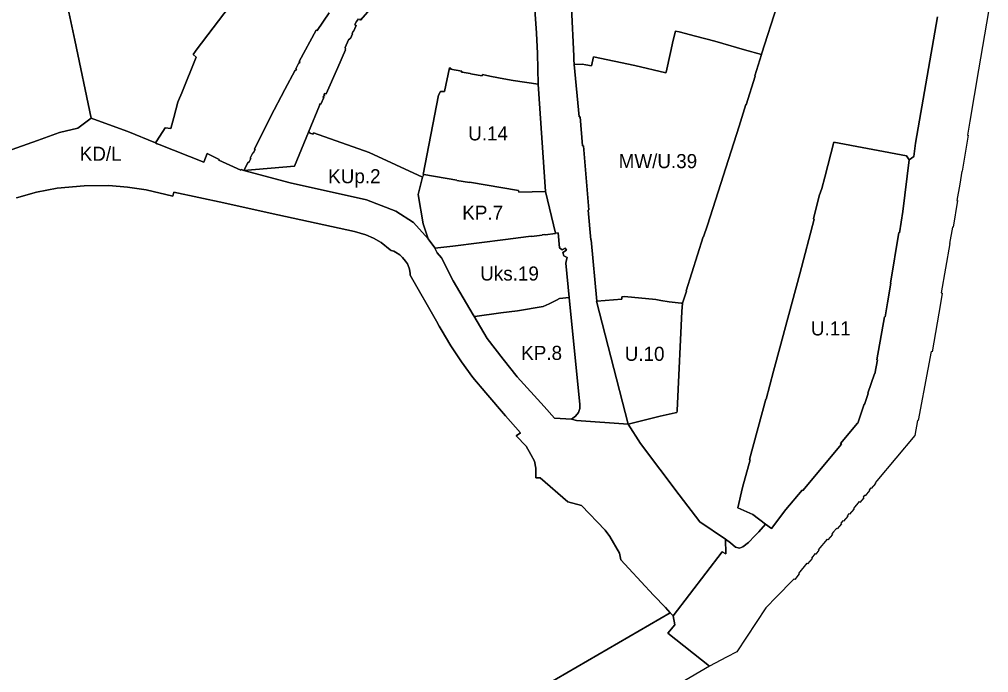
# Model space of a CAD drawing. Extents: x 7423367 to 7424726, y 5546744 to 5548391.
# Drawn here: x 7423781.7 to 7424125.7, y 5546954.8 to 5547186.6 of the extents above; entities that cross this region are included whole.
import ezdxf

# ---------------------------------------------------------------- set-up
doc = ezdxf.new("R2010")
doc.units = 0
doc.layers.add('linie_rozgraniczajace', color=7, linetype='Continuous')
doc.layers.add('oznaczenia_przeznaczen', color=7, linetype='Continuous')

msp = doc.modelspace()

# ---------------------------------------------------------------- linework, layer by layer
at = {"layer": 'linie_rozgraniczajace'}
for points in [[(7423780.9, 5547277.38), (7423781.77, 5547273.48), (7423781.99, 5547272.51), (7423786.19, 5547252.01), (7423786.97, 5547247.83), (7423787.16, 5547246.93), (7423787.29, 5547246.31), (7423798.24, 5547194.18), (7423801.4, 5547179.17), (7423807.26, 5547151.49), (7423802.44, 5547148.02), (7423795.99, 5547146.38), (7423788.2, 5547143.63), (7423771.74, 5547137.77)], [(7423858.41, 5547194.06), (7423844.47, 5547175.64), (7423844.19, 5547175.25), (7423843.38, 5547174.13), (7423844.5, 5547173.17), (7423839.34, 5547160.51), (7423838.19, 5547157.76), (7423837.93, 5547157.22), (7423836.5, 5547151.78), (7423835.47, 5547147.86), (7423833.44, 5547148.1), (7423830.48, 5547143.5), (7423830.02, 5547142.81), (7423820.24, 5547146.75), (7423817.3, 5547147.86), (7423807.26, 5547151.49), (7423801.4, 5547179.17), (7423798.24, 5547194.18)], [(7423891.7, 5547188.9), (7423887.37, 5547182.59), (7423887.1, 5547182.7), (7423881.04, 5547171.58), (7423881.33, 5547171.45), (7423881.13, 5547171.04), (7423880.91, 5547171.14), (7423879.9, 5547168.98), (7423880.13, 5547168.87), (7423879.91, 5547168.4), (7423879.61, 5547168.54), (7423875.98, 5547161.68), (7423870.92, 5547151.93), (7423865.17, 5547140.52), (7423865.45, 5547140.38), (7423864.75, 5547139.13), (7423864.54, 5547139.23), (7423863.62, 5547137.35), (7423863.92, 5547137.2), (7423863.18, 5547135.83), (7423862.93, 5547135.95), (7423861.44, 5547132.9), (7423860.42, 5547133.31), (7423860.32, 5547133.06), (7423852.49, 5547136.55), (7423852.62, 5547136.85), (7423848.42, 5547138.97), (7423847.19, 5547135.9), (7423831.4, 5547142.2), (7423831.38, 5547142.12), (7423830.67, 5547142.36), (7423830.02, 5547142.81), (7423830.48, 5547143.5), (7423833.44, 5547148.1), (7423835.47, 5547147.86), (7423836.5, 5547151.78), (7423837.93, 5547157.22), (7423838.19, 5547157.76), (7423839.34, 5547160.51), (7423844.5, 5547173.17), (7423843.38, 5547174.13), (7423844.19, 5547175.25), (7423844.47, 5547175.64), (7423858.41, 5547194.06)], [(7423964.53, 5547191.7), (7423965.29, 5547181.66), (7423965.67, 5547174.43), (7423965.92, 5547163.59), (7423957, 5547164.92), (7423953.69, 5547165.41), (7423949.28, 5547166.32), (7423948.75, 5547166.43), (7423946.11, 5547166.98), (7423946, 5547166.49), (7423942.52, 5547167.17), (7423941.98, 5547167.28), (7423941.69, 5547167.33), (7423939.65, 5547167.68), (7423938.65, 5547167.85), (7423938.72, 5547168.15), (7423934.79, 5547168.94), (7423934.87, 5547169.29), (7423934.38, 5547169.38), (7423932.64, 5547160.97), (7423932.34, 5547160.92), (7423931.16, 5547161.02), (7423930.5, 5547159.71), (7423925.04, 5547131.55), (7423925.33, 5547131.5), (7423924.86, 5547130.54), (7423905.89, 5547139.29), (7423886.14, 5547146.28), (7423885.96, 5547145.79), (7423884.84, 5547146.22), (7423884.84, 5547146.37), (7423884.34, 5547146.58), (7423888.27, 5547155.95), (7423888.4, 5547156.57), (7423888.73, 5547156.53), (7423889.74, 5547158.86), (7423889.49, 5547159.08), (7423889.88, 5547159.51), (7423890.03, 5547159.36), (7423889.96, 5547159.89), (7423890.14, 5547160.29), (7423890.67, 5547160.1), (7423894.73, 5547169.53), (7423897.52, 5547175.75), (7423897.32, 5547175.85), (7423897.48, 5547176.16), (7423897.37, 5547176.59), (7423898.6, 5547179.34), (7423898.98, 5547179.61), (7423899.11, 5547179.88), (7423899.25, 5547179.81), (7423899.96, 5547181.47), (7423899.82, 5547181.54), (7423900.2, 5547182.37), (7423900.36, 5547182.3), (7423901.22, 5547184.35), (7423900.91, 5547184.45), (7423900.81, 5547184.72), (7423901.41, 5547185.86), (7423902.14, 5547186.78)], [(7423902.4, 5547186.79), (7423902.85, 5547186.33), (7423908.05, 5547192.2)], [(7423908.05, 5547192.2), (7423902.85, 5547186.33), (7423902.4, 5547186.79)], [(7423977.66, 5547190.74), (7423978.47, 5547173.56), (7423978.49, 5547172.31), (7423978.6, 5547170.54), (7423980.47, 5547151.97), (7423980.77, 5547151.99), (7423981.64, 5547141.7), (7423981.9, 5547141.72), (7423983.87, 5547118.93), (7423983.64, 5547118.91), (7423984.5, 5547108.31), (7423984.69, 5547108.3), (7423986.71, 5547086.59), (7423986.53, 5547086.58), (7423997.8, 5547042.89), (7423979.41, 5547044.27), (7423977.65, 5547044.77), (7423979.16, 5547045.81), (7423980.17, 5547047.1), (7423980.61, 5547048.45), (7423980.68, 5547049.87), (7423976.85, 5547087.87), (7423975.63, 5547100.01), (7423975.89, 5547101.21), (7423976.16, 5547102.04), (7423974.94, 5547102.62), (7423974.67, 5547103.88), (7423975.91, 5547104.63), (7423975.49, 5547105.42), (7423974.36, 5547104.76), (7423973.42, 5547105.49), (7423973.02, 5547110.78), (7423972.03, 5547110.7), (7423968.48, 5547125.5), (7423965.92, 5547163.59), (7423965.67, 5547174.43), (7423965.29, 5547181.66), (7423964.53, 5547191.7)], [(7424050.63, 5547191.5), (7424045.15, 5547174.18), (7424045.13, 5547174.13), (7424039.15, 5547175.81), (7424028.56, 5547178.81), (7424021.67, 5547180.59), (7424015.88, 5547182.09), (7424014.6, 5547182.4), (7424013.78, 5547179.16), (7424012.82, 5547174.8), (7424011.29, 5547167.87), (7424011.23, 5547167.62), (7424000.16, 5547170.23), (7423985.51, 5547173.3), (7423984.79, 5547170.02), (7423982.81, 5547170.41), (7423981.42, 5547170.69), (7423978.6, 5547170.54), (7423978.49, 5547172.31), (7423978.47, 5547173.56), (7423977.66, 5547190.74)], [(7424107.64, 5547187.5), (7424099.83, 5547142.6), (7424099.19, 5547137.86), (7424097.5, 5547136.71), (7424096.59, 5547138.15), (7424070.83, 5547142.94), (7424069.78, 5547138.84), (7424067.62, 5547130.53), (7424066.54, 5547126.6), (7424065.64, 5547123.91), (7424063.54, 5547115.78), (7424063.79, 5547115.72), (7424058.77, 5547096.34), (7424053.24, 5547076.12), (7424051.97, 5547071.34), (7424049.44, 5547061.74), (7424046.77, 5547051.8), (7424046.62, 5547051.84), (7424040.92, 5547030.37), (7424041.06, 5547030.34), (7424038.39, 5547020.46), (7424036.72, 5547013.28), (7424042.03, 5547010.92), (7424046.6, 5547007.5), (7424044.15, 5547004.76), (7424042.71, 5547003.3), (7424040.46, 5547000.91), (7424038.52, 5546999.46), (7424037.33, 5546998.96), (7424035.88, 5546999.31), (7424034.18, 5547000.81), (7424032.38, 5547002.09), (7424023.2, 5547008.35), (7424015.95, 5547017.89), (7424002.22, 5547036.1), (7423997.8, 5547042.89), (7424009.16, 5547045.8), (7424014.48, 5547046.97), (7424015.12, 5547047.12), (7424015.14, 5547047.51), (7424015.16, 5547047.82), (7424015.28, 5547050.25), (7424016.86, 5547082.91), (7424017.03, 5547085.83), (7424018.53, 5547090.19), (7424018.4, 5547090.25), (7424024.42, 5547109.38), (7424024.59, 5547109.36), (7424025.98, 5547113.6), (7424037.14, 5547148.68), (7424039.54, 5547156.32), (7424039.64, 5547156.29), (7424042.9, 5547166.44), (7424042.75, 5547166.49), (7424045.13, 5547174.13), (7424045.15, 5547174.18), (7424050.63, 5547191.5)], [(7424125.73, 5547189.33), (7424122.09, 5547168.69), (7424119.09, 5547150.42), (7424118.27, 5547145.51), (7424118.42, 5547145.49), (7424116.33, 5547132.74), (7424116.19, 5547132.76), (7424115.51, 5547128.11), (7424114.5, 5547122.35), (7424114.65, 5547122.32), (7424113.11, 5547112.86), (7424112.96, 5547112.89), (7424111.82, 5547107.08), (7424111.98, 5547107.05), (7424108.93, 5547089.49), (7424109.27, 5547089.43), (7424108.63, 5547085.75), (7424105.64, 5547068.62), (7424105.33, 5547068.67), (7424104.2, 5547062.5), (7424100.74, 5547044.2), (7424100.51, 5547044.24), (7424099.56, 5547038.88), (7424086.03, 5547022.84), (7424085.41, 5547022.1), (7424085.6, 5547021.95), (7424084.01, 5547020.08), (7424083.81, 5547020.24), (7424083.3, 5547019.58), (7424083.51, 5547019.42), (7424081.88, 5547017.57), (7424081.7, 5547017.74), (7424081.15, 5547017.05), (7424081.45, 5547016.77), (7424080.08, 5547015.16), (7424079.73, 5547015.46), (7424077.72, 5547013), (7424077.92, 5547012.84), (7424076.36, 5547011), (7424076.16, 5547011.17), (7424075.57, 5547010.46), (7424075.77, 5547010.3), (7424074.19, 5547008.49), (7424074.02, 5547008.63), (7424073.32, 5547007.78), (7424073.55, 5547007.6), (7424071.96, 5547005.78), (7424071.73, 5547005.96), (7424070.62, 5547004.7), (7424070.04, 5547004), (7424070.27, 5547003.81), (7424068.7, 5547001.93), (7424068.46, 5547002.13), (7424065.28, 5546998.39), (7424065.51, 5546998.19), (7424064.4, 5546996.85), (7424064.17, 5546997.04), (7424062.86, 5546995.45), (7424063.09, 5546995.27), (7424061.48, 5546993.39), (7424061.26, 5546993.58), (7424058.24, 5546990.01), (7424058.46, 5546989.82), (7424056.94, 5546987.88), (7424056.72, 5546988.08), (7424056.23, 5546987.56), (7424050.53, 5546981.81), (7424046.67, 5546977.82), (7424036.4, 5546962.18), (7424032.69, 5546960.23), (7424026.71, 5546957.08), (7424011.83, 5546968.85), (7424014.42, 5546971.71), (7424013.75, 5546974.92), (7424031.19, 5546997.69), (7424032.43, 5546996.97), (7424032.38, 5547002.09), (7424034.18, 5547000.81), (7424035.88, 5546999.31), (7424037.33, 5546998.96), (7424038.52, 5546999.46), (7424040.46, 5547000.91), (7424042.71, 5547003.3), (7424044.15, 5547004.76), (7424046.6, 5547007.5), (7424048.68, 5547005.93), (7424053.78, 5547012.63), (7424059.55, 5547019.59), (7424059.8, 5547019.42), (7424073.46, 5547035.91), (7424073.22, 5547036.09), (7424079.18, 5547043.35), (7424079.29, 5547043.28), (7424081.53, 5547050.02), (7424081.68, 5547049.96), (7424083.01, 5547053.83), (7424082.87, 5547053.89), (7424085.21, 5547060.84), (7424085.39, 5547060.77), (7424086.28, 5547065.77), (7424086.11, 5547065.8), (7424088.8, 5547080.99), (7424088.96, 5547080.97), (7424089.83, 5547085.96), (7424091.03, 5547092.98), (7424090.86, 5547093.02), (7424093.89, 5547110.9), (7424094.06, 5547110.87), (7424095.26, 5547118.38), (7424097.5, 5547136.71), (7424099.19, 5547137.86), (7424099.83, 5547142.6), (7424107.64, 5547187.5)], [(7423902.14, 5547186.78), (7423901.41, 5547185.86), (7423900.81, 5547184.72), (7423900.91, 5547184.45), (7423901.22, 5547184.35), (7423900.36, 5547182.3), (7423900.2, 5547182.37), (7423899.82, 5547181.54), (7423899.96, 5547181.47), (7423899.25, 5547179.81), (7423899.11, 5547179.88), (7423898.98, 5547179.61), (7423898.6, 5547179.34), (7423897.37, 5547176.59), (7423897.48, 5547176.16), (7423897.32, 5547175.85), (7423897.52, 5547175.75), (7423894.73, 5547169.53), (7423890.67, 5547160.1), (7423890.14, 5547160.29), (7423889.96, 5547159.89), (7423890.03, 5547159.36), (7423889.88, 5547159.51), (7423889.49, 5547159.08), (7423889.74, 5547158.86), (7423888.73, 5547156.53), (7423888.4, 5547156.57), (7423888.27, 5547155.95), (7423884.34, 5547146.58), (7423879.39, 5547134.52), (7423861.44, 5547132.9), (7423862.93, 5547135.95), (7423863.18, 5547135.83), (7423863.92, 5547137.2), (7423863.62, 5547137.35), (7423864.54, 5547139.23), (7423864.75, 5547139.13), (7423865.45, 5547140.38), (7423865.17, 5547140.52), (7423870.92, 5547151.93), (7423875.98, 5547161.68), (7423879.61, 5547168.54), (7423879.91, 5547168.4), (7423880.13, 5547168.87), (7423879.9, 5547168.98), (7423880.91, 5547171.14), (7423881.13, 5547171.04), (7423881.33, 5547171.45), (7423881.04, 5547171.58), (7423887.1, 5547182.7), (7423887.37, 5547182.59), (7423891.7, 5547188.9)], [(7423771.74, 5547137.77), (7423788.2, 5547143.63), (7423795.99, 5547146.38), (7423802.44, 5547148.02), (7423807.26, 5547151.49), (7423817.3, 5547147.86), (7423820.24, 5547146.75), (7423830.02, 5547142.81), (7423830.67, 5547142.36), (7423831.38, 5547142.12), (7423831.4, 5547142.2), (7423847.19, 5547135.9), (7423848.42, 5547138.97), (7423852.62, 5547136.85), (7423852.49, 5547136.55), (7423860.32, 5547133.06), (7423860.42, 5547133.31), (7423861.44, 5547132.9), (7423877.87, 5547128.58), (7423904.89, 5547122.59), (7423915.35, 5547118.56), (7423921.65, 5547114.49), (7423926.87, 5547108.65), (7423929.14, 5547105.52), (7423929.2, 5547105.41), (7423930.06, 5547103.69), (7423931.51, 5547102.01), (7423935.71, 5547093.74), (7423942.8, 5547081.71), (7423942.98, 5547081.39), (7423947.77, 5547073.3), (7423953.43, 5547066.01), (7423958.43, 5547059.72), (7423968.05, 5547049.27), (7423971.64, 5547045.06), (7423977.65, 5547044.77), (7423979.41, 5547044.27), (7423997.8, 5547042.89), (7424002.22, 5547036.1), (7424015.95, 5547017.89), (7424023.2, 5547008.35), (7424032.38, 5547002.09), (7424032.43, 5546996.97), (7424031.19, 5546997.69), (7424013.75, 5546974.92), (7424012.71, 5546976.05), (7424011.04, 5546977.88), (7424006.85, 5546982.3), (7423998.1, 5546991.7), (7423995.21, 5546994.8), (7423994.72, 5546997.14), (7423991.35, 5547003.15), (7423989.61, 5547005.39), (7423981.23, 5547014.14), (7423976.37, 5547015.44), (7423966.53, 5547023.9), (7423965.01, 5547023.9), (7423965.07, 5547027.35), (7423964.54, 5547029.86), (7423963.28, 5547032.24), (7423961.57, 5547035.12), (7423958, 5547038.83), (7423959.54, 5547039.82), (7423954.24, 5547045.94), (7423947.27, 5547054.01), (7423942.71, 5547059.52), (7423938.61, 5547065.04), (7423934.84, 5547070.76), (7423931.45, 5547076.48), (7423930.72, 5547077.75), (7423929.76, 5547079.44), (7423920.48, 5547095.76), (7423920.43, 5547096.36), (7423920.14, 5547097.94), (7423919.74, 5547099.25), (7423919.43, 5547099.79), (7423918.81, 5547100.8), (7423917.77, 5547102.1), (7423916.75, 5547103.03), (7423915.23, 5547104), (7423914.59, 5547104.3), (7423913.75, 5547104.61), (7423913.3, 5547104.76), (7423910.11, 5547107.44), (7423907.48, 5547108.99), (7423904.73, 5547110.11), (7423900.69, 5547111.27), (7423870.8, 5547117.86), (7423854.32, 5547121.53), (7423836.56, 5547125.29), (7423836.22, 5547123.82), (7423826.7, 5547126.03), (7423820.12, 5547127.03), (7423813.54, 5547127.58), (7423804.69, 5547127.48), (7423795.11, 5547126.62), (7423787.83, 5547125.26), (7423780.68, 5547123.28)], [(7423780.68, 5547123.28), (7423787.83, 5547125.26), (7423795.11, 5547126.62), (7423804.69, 5547127.48), (7423813.54, 5547127.58), (7423820.12, 5547127.03), (7423826.7, 5547126.03), (7423836.22, 5547123.82), (7423836.56, 5547125.29), (7423854.32, 5547121.53), (7423870.8, 5547117.86), (7423900.69, 5547111.27), (7423904.73, 5547110.11), (7423907.48, 5547108.99), (7423910.11, 5547107.44), (7423913.3, 5547104.76), (7423913.75, 5547104.61), (7423914.59, 5547104.3), (7423915.23, 5547104), (7423916.75, 5547103.03), (7423917.77, 5547102.1), (7423918.81, 5547100.8), (7423919.43, 5547099.79), (7423919.74, 5547099.25), (7423920.14, 5547097.94), (7423920.43, 5547096.36), (7423920.48, 5547095.76), (7423929.76, 5547079.44), (7423930.72, 5547077.75), (7423931.45, 5547076.48), (7423934.84, 5547070.76), (7423938.61, 5547065.04), (7423942.71, 5547059.52), (7423947.27, 5547054.01), (7423954.24, 5547045.94), (7423959.54, 5547039.82), (7423958, 5547038.83), (7423961.57, 5547035.12), (7423963.28, 5547032.24), (7423964.54, 5547029.86), (7423965.07, 5547027.35), (7423965.01, 5547023.9), (7423966.53, 5547023.9), (7423976.37, 5547015.44), (7423981.23, 5547014.14), (7423989.61, 5547005.39), (7423991.35, 5547003.15), (7423994.72, 5546997.14), (7423995.21, 5546994.8), (7423998.1, 5546991.7), (7424006.85, 5546982.3), (7424011.04, 5546977.88), (7424012.71, 5546976.05), (7423939.4, 5546933.41)], [(7423939.4, 5546933.41), (7424012.71, 5546976.05), (7424013.75, 5546974.92), (7424014.42, 5546971.71), (7424011.83, 5546968.85), (7424026.71, 5546957.08), (7423900.72, 5546883.26)]]:
    msp.add_lwpolyline(points, dxfattribs=at)
for points in [[(7423978.6, 5547170.54), (7423981.42, 5547170.69), (7423982.81, 5547170.41), (7423984.79, 5547170.02), (7423985.51, 5547173.3), (7424000.16, 5547170.23), (7424011.23, 5547167.62), (7424011.29, 5547167.87), (7424012.82, 5547174.8), (7424013.78, 5547179.16), (7424014.6, 5547182.4), (7424015.88, 5547182.09), (7424021.67, 5547180.59), (7424028.56, 5547178.81), (7424039.15, 5547175.81), (7424045.13, 5547174.13), (7424042.75, 5547166.49), (7424042.9, 5547166.44), (7424039.64, 5547156.29), (7424039.54, 5547156.32), (7424037.14, 5547148.68), (7424025.98, 5547113.6), (7424024.59, 5547109.36), (7424024.42, 5547109.38), (7424018.4, 5547090.25), (7424018.53, 5547090.19), (7424017.03, 5547085.83), (7424016.58, 5547085.88), (7424012.34, 5547086.35), (7424009.45, 5547086.78), (7424007.66, 5547087.12), (7423996.56, 5547088.21), (7423995.55, 5547088.15), (7423995.57, 5547087.34), (7423986.71, 5547086.59), (7423984.69, 5547108.3), (7423984.5, 5547108.31), (7423983.64, 5547118.91), (7423983.87, 5547118.93), (7423981.9, 5547141.72), (7423981.64, 5547141.7), (7423980.77, 5547151.99), (7423980.47, 5547151.97)], [(7423925.04, 5547131.55), (7423930.5, 5547159.71), (7423931.16, 5547161.02), (7423932.34, 5547160.92), (7423932.64, 5547160.97), (7423934.38, 5547169.38), (7423934.87, 5547169.29), (7423934.79, 5547168.94), (7423938.72, 5547168.15), (7423938.65, 5547167.85), (7423939.65, 5547167.68), (7423941.69, 5547167.33), (7423941.98, 5547167.28), (7423942.52, 5547167.17), (7423946, 5547166.49), (7423946.11, 5547166.98), (7423948.75, 5547166.43), (7423949.28, 5547166.32), (7423953.69, 5547165.41), (7423957, 5547164.92), (7423965.92, 5547163.59), (7423968.48, 5547125.5), (7423959.06, 5547125.26), (7423958.93, 5547125.89), (7423941.52, 5547128.79), (7423941.5, 5547128.65), (7423937.01, 5547129.42), (7423937.04, 5547129.56), (7423925.33, 5547131.5)], [(7423861.44, 5547132.9), (7423879.39, 5547134.52), (7423884.34, 5547146.58), (7423884.84, 5547146.37), (7423884.84, 5547146.22), (7423885.96, 5547145.79), (7423886.14, 5547146.28), (7423905.89, 5547139.29), (7423924.86, 5547130.54), (7423923.28, 5547124.45), (7423925.1, 5547114.02), (7423926.87, 5547108.65), (7423921.65, 5547114.49), (7423915.35, 5547118.56), (7423904.89, 5547122.59), (7423877.87, 5547128.58)], [(7424036.72, 5547013.28), (7424038.39, 5547020.46), (7424041.06, 5547030.34), (7424040.92, 5547030.37), (7424046.62, 5547051.84), (7424046.77, 5547051.8), (7424049.44, 5547061.74), (7424051.97, 5547071.34), (7424053.24, 5547076.12), (7424058.77, 5547096.34), (7424063.79, 5547115.72), (7424063.54, 5547115.78), (7424065.64, 5547123.91), (7424066.54, 5547126.6), (7424067.62, 5547130.53), (7424069.78, 5547138.84), (7424070.83, 5547142.94), (7424096.59, 5547138.15), (7424097.5, 5547136.71), (7424095.26, 5547118.38), (7424094.06, 5547110.87), (7424093.89, 5547110.9), (7424090.86, 5547093.02), (7424091.03, 5547092.98), (7424089.83, 5547085.96), (7424088.96, 5547080.97), (7424088.8, 5547080.99), (7424086.11, 5547065.8), (7424086.28, 5547065.77), (7424085.39, 5547060.77), (7424085.21, 5547060.84), (7424082.87, 5547053.89), (7424083.01, 5547053.83), (7424081.68, 5547049.96), (7424081.53, 5547050.02), (7424079.29, 5547043.28), (7424079.18, 5547043.35), (7424073.22, 5547036.09), (7424073.46, 5547035.91), (7424059.8, 5547019.42), (7424059.55, 5547019.59), (7424053.78, 5547012.63), (7424048.68, 5547005.93), (7424046.6, 5547007.5), (7424042.03, 5547010.92)], [(7423923.28, 5547124.45), (7423924.86, 5547130.54), (7423925.33, 5547131.5), (7423937.04, 5547129.56), (7423937.01, 5547129.42), (7423941.5, 5547128.65), (7423941.52, 5547128.79), (7423958.93, 5547125.89), (7423959.06, 5547125.26), (7423968.48, 5547125.5), (7423972.03, 5547110.7), (7423972.03, 5547110.56), (7423968.3, 5547110.06), (7423968.24, 5547110.24), (7423967.24, 5547110.11), (7423967.23, 5547109.97), (7423963.49, 5547109.48), (7423963.46, 5547109.63), (7423962.4, 5547109.54), (7423954.3, 5547108.48), (7423935.54, 5547106.05), (7423929.2, 5547105.41), (7423929.14, 5547105.52), (7423926.87, 5547108.65), (7423925.1, 5547114.02)], [(7423929.2, 5547105.41), (7423935.54, 5547106.05), (7423954.3, 5547108.48), (7423962.4, 5547109.54), (7423963.46, 5547109.63), (7423963.49, 5547109.48), (7423967.23, 5547109.97), (7423967.24, 5547110.11), (7423968.24, 5547110.24), (7423968.3, 5547110.06), (7423972.03, 5547110.56), (7423972.03, 5547110.7), (7423973.02, 5547110.78), (7423973.42, 5547105.49), (7423974.36, 5547104.76), (7423975.49, 5547105.42), (7423975.91, 5547104.63), (7423974.67, 5547103.88), (7423974.94, 5547102.62), (7423976.16, 5547102.04), (7423975.89, 5547101.21), (7423975.63, 5547100.01), (7423976.85, 5547087.87), (7423973.48, 5547087.56), (7423972.97, 5547087.33), (7423972.9, 5547087.14), (7423969.76, 5547085.68), (7423967.69, 5547084.73), (7423958.54, 5547083.16), (7423952.67, 5547082.4), (7423943.4, 5547081.2), (7423943.18, 5547081.25), (7423942.98, 5547081.39), (7423942.8, 5547081.71), (7423935.71, 5547093.74), (7423931.51, 5547102.01), (7423930.06, 5547103.69)], [(7423942.98, 5547081.39), (7423943.18, 5547081.25), (7423943.4, 5547081.2), (7423952.67, 5547082.4), (7423958.54, 5547083.16), (7423967.69, 5547084.73), (7423969.76, 5547085.68), (7423972.9, 5547087.14), (7423972.97, 5547087.33), (7423973.48, 5547087.56), (7423976.85, 5547087.87), (7423980.68, 5547049.87), (7423980.61, 5547048.45), (7423980.17, 5547047.1), (7423979.16, 5547045.81), (7423977.65, 5547044.77), (7423971.64, 5547045.06), (7423968.05, 5547049.27), (7423958.43, 5547059.72), (7423953.43, 5547066.01), (7423947.77, 5547073.3)], [(7423986.53, 5547086.58), (7423986.71, 5547086.59), (7423995.57, 5547087.34), (7423995.55, 5547088.15), (7423996.56, 5547088.21), (7424007.66, 5547087.12), (7424009.45, 5547086.78), (7424012.34, 5547086.35), (7424016.58, 5547085.88), (7424017.03, 5547085.83), (7424016.86, 5547082.91), (7424015.28, 5547050.25), (7424015.16, 5547047.82), (7424015.14, 5547047.51), (7424015.12, 5547047.12), (7424014.48, 5547046.97), (7424009.16, 5547045.8), (7423997.8, 5547042.89)]]:
    msp.add_lwpolyline(points, close=True, dxfattribs=at)

# ---------------------------------------------------------------- texts
at = {"layer": 'oznaczenia_przeznaczen'}
for s, p in [('U.14', (7423941.03, 5547143.61)), ('KD/L', (7423803.16, 5547136.38)), ('MW/U.39', (7423994.43, 5547133.77)), ('KUp.2', (7423891.34, 5547128.41)), ('KP.7', (7423938.93, 5547115.46)), ('Uks.19', (7423945.31, 5547093.9)), ('U.11', (7424062.66, 5547074.42)), ('KP.8', (7423959.84, 5547065.73)), ('U.10', (7423996.58, 5547065.41))]:
    msp.add_text(s, height=5, dxfattribs=at).set_placement(p)

doc.saveas('drawing.dxf')
